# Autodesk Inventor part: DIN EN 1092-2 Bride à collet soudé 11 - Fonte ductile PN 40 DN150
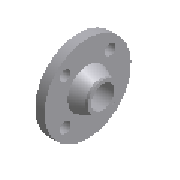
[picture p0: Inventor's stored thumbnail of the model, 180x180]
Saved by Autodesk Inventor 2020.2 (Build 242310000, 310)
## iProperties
Created: 2019-01
Part Number: DIN EN 1092-2 Bride à collet soudé 11 - Fonte ductile PN 40 DN150
Material: Fonte, ductile
Description: Bride
Document SubType Name: Modeling
Standard: DIN EN 1092-2
Designer: t.sancier
Standards Organization: DIN
Language: fr-FR
Size Designation: DN150
Categories: <MemberInstance><Categories><Category DisplayName="Tubes et tuyaux" InternalName="4347fa0f-2144-441d-94cd-e3e15c92b736" Mnemonic="TUBEANDPIPE"><CategoryParamete
Density: 7.15 g/cm^3
Appearance: Fonte grise
NAME: PIPING: DIN EN 1092-2 Welding Neck Flange Type 11 - PN 40 Ductile Iron
DATA: <meta><inlinegroups number="1" deflen="4.5"></inlinegroups><connections number="2"></connections><angles><a>3.14159265358979</a></angles></meta>
IsCustomPart: 0
Author: t.sancier
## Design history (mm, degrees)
sketch "Sketch1"
  geometry: L1 (0, 0)-(75, 0) reference; L2 (0, 75)-(0, 105.5); L3 (0, 105.5)-(3, 105.5); L4 (3, 150)-(26, 150); L5 (0, 75)-(0, 0); L6 (3, 150)-(3, 105.5); L7 (26, 150)-(26, 96); L8 (0, 75)-(75, 75); L9 (75, 75)-(75, 81); L10 (75, 81)-(67.5, 81); L11 (67.5, 81)-(26, 96); L12 (75, 75)-(75, 0)
  constraints: 24 end point, 5 perpendicular, 3 parallel, 1 collinear, 1 horizontal
  dimensions: "d0" = 211 diameter of L3 L1 (= D1); "d1" = 300 diameter of L4 L1 (= D); "d2" = 26 distance between parallel lines of L2 L7 (= C1); "d3" = 75 distance between parallel lines of L9 L2 (= H2); "d4" = 6 distance between parallel lines of L8 L10 (= t); "d5" = 192 diameter of L7.end L1 (= N3); "d6" = 3 distance between parallel lines of L2 L6 (= F1); "d12" = 150 diameter of L8 L1 (= ID); "d13" = 7.5 distance of L9.end L10.end (= 0.1 x H2)
revolve "Revolution1" stored, may be unused: angle "d11" = 90 deg
pattern_circular "Circular Pattern1" dims angle "d10" = 360 deg
workaxis "Work Axis1"
workpoint "Work Point1"
workaxis "Work Axis2"
workpoint "Work Point2"
body "Solid1"
sketch "Sketch2"
  geometry: L1 (0, 0)-(0, 125); L2 (0, 0)-(47.835, 115.485); C1 r 105.5 at (0, 0) reference; C2 r 150 at (0, 0) reference; C3 r 14 at (47.835, 115.485); A1 r 125 centre (0, 0) between (47.835, 115.485) and (0, 125)
  constraints: 4 end point, 2 centre point, 2 coincident, 2 point on circle, 1 vertical
  dimensions: "d14" = 28 diameter of C3 (= L); "d15" = 125 distance of L2.start L2.end (= 0.5 x K1); "d16" = 22.5 deg angle of L2 L1 (computed from NU)
extrude "Extrusion1" cut sketch "Sketch2" distance "d7" = 26 (= C1); taper "d8" = 0 deg
other parameters: "C1" = 26 [user parameter; used in 2 equation terms], "D" = 300 [user parameter; used in 1 equation term], "L" = 28 [user parameter; used in 1 equation term], "N3" = 192 [user parameter; used in 1 equation term], "D1" = 211 [user parameter; used in 1 equation term], "H2" = 75 [user parameter; used in 2 equation terms], "t" = 6 [user parameter; used in 1 equation term], "F1" = 3 [user parameter; used in 1 equation term], "ID" = 150 [user parameter; used in 1 equation term], "Size_Designation" = 12.345 [user parameter]
